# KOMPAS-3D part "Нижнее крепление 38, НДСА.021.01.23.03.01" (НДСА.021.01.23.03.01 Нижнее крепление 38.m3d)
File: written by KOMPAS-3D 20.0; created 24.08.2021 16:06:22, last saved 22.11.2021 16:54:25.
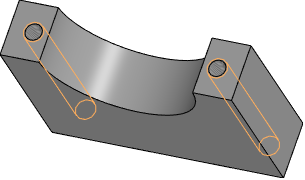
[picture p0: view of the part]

Document properties: Полное имя файла: C:\Users\s.pischagina\Desktop\PLM\НДСА.021.01.23.03.01 Нижнее крепление 38.m3d

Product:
- Part/product: Нижнее крепление 38  | designation НДСА.021.01.23.03.01
    Материал: АМг6  ГОСТ 4784-2019 (density 2640 kg/m3)
    Масса: 0.0662558
    additional columns: <item xmlns="http://appius.ru/pdm" xmlns:xs="http://www.w3.org/2001/XMLSchema" x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; <item xmlns="http://appius.ru/pdm" xmlns:xs="http://www.w3.org/2001/XMLSchema" x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; <item xmlns="http://appius.ru/pdm" xmlns:xs="http://www.w3.org/2001/XMLSchema" x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; <item xmlns="http://appius.ru/pdm" xmlns:xs="http://www.w3.org/2001/XMLSchema" x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; <item xmlns="http://appius.ru/pdm" xmlns:xs="http://www.w3.org/2001/XMLSchema" x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
    source file: НДСА.002.01.06.01.00 Нижнее крепление 38.cdw, НДСА.021.01.23.03.01 Нижнее крепление 38.cdw

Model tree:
1. Эскиз:1
2. Элемент выдавливания:1
     Расстояние 1 = 80
3. Эскиз:2  (with: Элемент выдавливания:1)
4. Элемент выдавливания:2
5. Эскиз:3  (with: Элемент выдавливания:1, Элемент выдавливания:2)
6. Элемент выдавливания:3
7. Эскиз:4  (with: Элемент выдавливания:3)
8. Элемент выдавливания:4
     Расстояние 1 = 28
9. Эскиз:15  (with: Элемент выдавливания:3)
10. Элемент выдавливания:6
     Расстояние 2 = 52
11. Элемент выдавливания:11  (with: Элемент выдавливания:1)
     Расстояние 2 = 10
12. Эскиз:25  (with: Элемент выдавливания:11)
13. Элемент выдавливания:12
14. Условное изображение резьбы:4  (with: Элемент выдавливания:12)  (labels: M5; cil0_24705-2004 coarse)
     Длина резьбы = 42; Шаг резьбы = 0.8; Номинальный диаметр резьбы = 5
15. Подгонка:4  (with: Элемент выдавливания:12)
16. Условное изображение резьбы:5  (with: Элемент выдавливания:12)  (labels: M5; cil0_24705-2004 coarse)
     Длина резьбы = 42; Шаг резьбы = 0.8; Номинальный диаметр резьбы = 5
17. Подгонка:5  (with: Элемент выдавливания:12)  (labels: АМг6  ГОСТ 4784-2019)

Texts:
  НДСА.021.01.23.03.01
